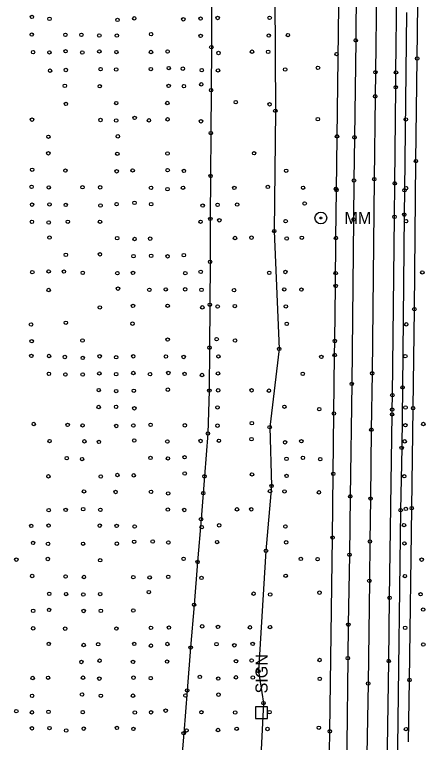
# Model space of a CAD drawing. Extents: x 20503438 to 20508873, y 7964251 to 7984667.
# Drawn here: x 20506372.5 to 20506616, y 7966287.3 to 7966710.9 of the extents above; entities that cross this region are included whole.
import ezdxf

# ---------------------------------------------------------------- set-up
doc = ezdxf.new("R2010")
doc.units = 0
for name, color, linetype in [('SurBreakLine', 7, 'Continuous'), ('SurDrainageArrowDown', 7, 'Continuous'), ('SurEdgeRoadPaved', 7, 'Continuous'), ('SurEdgeShoulderPaved', 7, 'Continuous'), ('SurGuardRailCable', 7, 'Continuous'), ('SurPointsNonDTM', 7, 'Continuous'), ('SurRoadPoints', 7, 'Continuous'), ('SurSurveyPoints', 7, 'Continuous')]:
    doc.layers.add(name, color=color, linetype=linetype)

msp = doc.modelspace()

# ---------------------------------------------------------------- linework, layer by layer
at = {"layer": 'SurBreakLine'}
msp.add_lwpolyline([(20506582.81, 7966724.92), (20506582.26, 7966677.31), (20506582.09, 7966663.27), (20506581.59, 7966615.11), (20506580.38, 7966502.13), (20506579.87, 7966469.3), (20506579.47, 7966429.21), (20506579.05, 7966404.24), (20506578.73, 7966381.34), (20506578.04, 7966321.61), (20506576.98, 7966259.67), (20506576.78, 7966244.96), (20506576.56, 7966215.41), (20506575.87, 7966179.43), (20506575.47, 7966138), (20506575.36, 7966120.77), (20506575.03, 7966091.32), (20506574.47, 7966046.48)], dxfattribs=at)
at = {"layer": 'SurDrainageArrowDown'}
for points in [[(20506523.75, 7966721.59), (20506524.08, 7966654.91), (20506523.46, 7966584.86), (20506526.32, 7966516.32), (20506520.79, 7966470.76), (20506521.88, 7966436.58), (20506518.64, 7966398.81), (20506514.26, 7966328.87), (20506517.2, 7966310.23), (20506515.68, 7966279.39), (20506513.5, 7966229.59), (20506515.33, 7966159.59), (20506514.55, 7966120.49), (20506514.84, 7966104.97), (20506511.67, 7966081.49), (20506510.59, 7966067.23)], [(20506487.04, 7966716.85), (20506486.89, 7966691.87), (20506486.74, 7966666.9), (20506486.58, 7966641.92), (20506486.43, 7966616.94), (20506486.28, 7966591.96), (20506486.13, 7966566.98), (20506485.98, 7966542.01), (20506485.83, 7966517.03), (20506485.68, 7966492.05), (20506484.9, 7966467.09), (20506482.89, 7966442.17), (20506480.87, 7966417.25), (20506478.86, 7966392.34), (20506476.85, 7966367.42), (20506474.83, 7966342.5), (20506472.82, 7966317.58), (20506470.8, 7966292.66), (20506468.79, 7966267.75)]]:
    msp.add_lwpolyline(points, dxfattribs=at)
at = {"layer": 'SurEdgeRoadPaved'}
for points in [[(20506571.13, 7966726.82), (20506570.83, 7966695.86), (20506570.09, 7966639.42), (20506569.8, 7966614.3), (20506569.59, 7966591.6), (20506568.51, 7966495.95), (20506567.62, 7966430.5), (20506567.22, 7966396.52), (20506566.49, 7966355.87), (20506566.21, 7966336.33), (20506565, 7966235.53), (20506564.23, 7966182.81), (20506563.62, 7966117.05), (20506563.45, 7966102.98), (20506562.98, 7966069.12), (20506561.69, 7965956.65)], [(20506586.39, 7966046.04), (20506586.58, 7966062.88), (20506587.24, 7966125.61), (20506587.67, 7966161.5), (20506587.93, 7966195.96), (20506590.01, 7966334.68), (20506590.5, 7966371.48), (20506591.96, 7966478.18), (20506591.99, 7966480.99), (20506592.1, 7966489.42), (20506593.34, 7966593.17), (20506593.52, 7966612.66), (20506594.1, 7966668.59), (20506594.21, 7966677.21), (20506594.79, 7966724.61)]]:
    msp.add_lwpolyline(points, dxfattribs=at)
at = {"layer": 'SurEdgeShoulderPaved'}
for points in [[(20506552.57, 7966028.45), (20506552.68, 7966057.72), (20506553.65, 7966115.57), (20506554.86, 7966229.07), (20506555.39, 7966269.1), (20506555.74, 7966293.81), (20506557.36, 7966406.54), (20506557.74, 7966443.63), (20506558.13, 7966478.73), (20506558.55, 7966512.75), (20506558.65, 7966520.93), (20506559.14, 7966552.93), (20506559.31, 7966580.85), (20506559.62, 7966608.8), (20506561.22, 7966731.44)], [(20506600.27, 7966712.13), (20506599.16, 7966608.62), (20506599.01, 7966594.45), (20506598.05, 7966493.9), (20506597.53, 7966458.7), (20506596.92, 7966422.46), (20506595.16, 7966284.71), (20506594.2, 7966234.33), (20506593.75, 7966203.67), (20506592.8, 7966094.73), (20506592.19, 7966059.31), (20506591.79, 7966030.9)]]:
    msp.add_lwpolyline(points, dxfattribs=at)
at = {"layer": 'SurGuardRailCable'}
msp.add_lwpolyline([(20506601.58, 7966287.7), (20506602.08, 7966323.65), (20506603.37, 7966423.64), (20506604.15, 7966481.82), (20506604.89, 7966539.46), (20506605.81, 7966625.62), (20506606.52, 7966685.31), (20506607.57, 7966764.47), (20506608.97, 7966864.46), (20506610.33, 7966964.45), (20506611.57, 7967064.43), (20506612.49, 7967145.99), (20506613.24, 7967217.79), (20506614.06, 7967289.17), (20506615.02, 7967359.71), (20506615.99, 7967430.36)], dxfattribs=at)
at = {"layer": 'SurPointsNonDTM'}
for centre in [(20506606.52, 7966685.31), (20506605.81, 7966625.62), (20506604.89, 7966539.46), (20506604.15, 7966481.82), (20506603.37, 7966423.64), (20506602.08, 7966323.65)]:
    msp.add_circle(centre, 1, dxfattribs=at)
at = {"layer": 'SurRoadPoints'}
msp.add_lwpolyline([(20506519.48, 7966304.63), (20506519.48, 7966304.63), (20506519.48, 7966308.06), (20506512.62, 7966308.06), (20506512.62, 7966301.2), (20506519.48, 7966301.2), (20506519.48, 7966304.63)], dxfattribs=at)
for radius in [3.43, 0.571]:
    msp.add_circle((20506550.55, 7966592.5), radius, dxfattribs=at)
at = {"layer": 'SurSurveyPoints'}
for centre in [(20506382.56, 7966709.49), (20506392.78, 7966708.38), (20506442.07, 7966708.66), (20506480.62, 7966708.52), (20506490.53, 7966708.88), (20506520.77, 7966708.94), (20506432.3, 7966707.76), (20506470.57, 7966708.12), (20506382.48, 7966699.22), (20506402.05, 7966699.05), (20506411.33, 7966699.09), (20506421.73, 7966698.69), (20506431.91, 7966698.64), (20506451.83, 7966699.44), (20506480.66, 7966698.44), (20506520.24, 7966698.63), (20506531.39, 7966698.92), (20506570.83, 7966695.86), (20506486.89, 7966691.87), (20506383.23, 7966688.99), (20506392.73, 7966688.86), (20506402.15, 7966689.51), (20506411.87, 7966688.78), (20506421.76, 7966689.43), (20506431.68, 7966689.04), (20506451.82, 7966689.06), (20506461.42, 7966689.35), (20506491.03, 7966688.52), (20506510.5, 7966689.26), (20506519.94, 7966689.16), (20506559.67, 7966687.88), (20506402.29, 7966678.63), (20506422.5, 7966679.08), (20506431.56, 7966678.92), (20506451.69, 7966679.13), (20506462.13, 7966679.73), (20506470.31, 7966679.37), (20506529.77, 7966678.9), (20506548.87, 7966679.86), (20506393.12, 7966678.21), (20506481.31, 7966678.54), (20506490.76, 7966678.38), (20506582.26, 7966677.31), (20506594.21, 7966677.21), (20506481.02, 7966670.25), (20506401.69, 7966669.42), (20506421.99, 7966669.14), (20506462.05, 7966669.34), (20506470.93, 7966669.18), (20506486.74, 7966666.9), (20506594.1, 7966668.59), (20506582.09, 7966663.27), (20506402.34, 7966658.87), (20506431.6, 7966659.37), (20506461.27, 7966659.38), (20506501.05, 7966659.92), (20506520.75, 7966658.66), (20506524.08, 7966654.91), (20506382.61, 7966649.72), (20506422.41, 7966649.52), (20506431.52, 7966649.25), (20506442.28, 7966650.73), (20506450.59, 7966649.31), (20506461.44, 7966649.88), (20506548.81, 7966649.99), (20506599.92, 7966649.86), (20506480.89, 7966648.77), (20506486.58, 7966641.92), (20506392.15, 7966639.77), (20506432.52, 7966639.99), (20506559.9, 7966640), (20506570.09, 7966639.42), (20506392.13, 7966630.14), (20506432.21, 7966629.89), (20506461.39, 7966630.01), (20506511.72, 7966630.18), (20506382.7, 7966620.55), (20506402.03, 7966620.1), (20506431.82, 7966619.67), (20506441.13, 7966620.17), (20506461.46, 7966620.31), (20506470.94, 7966619.9), (20506530.37, 7966619.97), (20506486.43, 7966616.94), (20506581.59, 7966615.11), (20506569.8, 7966614.3), (20506593.52, 7966612.66), (20506382.37, 7966610.63), (20506392.37, 7966610.27), (20506411.98, 7966610.37), (20506422.22, 7966610.35), (20506451.81, 7966610.07), (20506461.41, 7966609.27), (20506470.43, 7966610.1), (20506500.22, 7966610.01), (20506519.69, 7966610.58), (20506540.2, 7966610.11), (20506559.32, 7966609.51), (20506559.62, 7966608.8), (20506599.16, 7966608.62), (20506600.11, 7966609.85), (20506382.67, 7966600.27), (20506392.81, 7966600.38), (20506402.23, 7966600.1), (20506422.43, 7966599.78), (20506431.8, 7966600.54), (20506442.21, 7966601.33), (20506451.89, 7966600.54), (20506481.85, 7966599.71), (20506490.51, 7966600.15), (20506501.91, 7966600.3), (20506541.11, 7966600.94), (20506599.01, 7966594.45), (20506382.55, 7966590.28), (20506392.31, 7966589.85), (20506403.43, 7966590.32), (20506422.14, 7966590.29), (20506480.61, 7966590.29), (20506486.28, 7966591.96), (20506491.51, 7966591.14), (20506530.06, 7966590.65), (20506569.59, 7966591.6), (20506593.34, 7966593.17), (20506600.07, 7966590.64), (20506523.46, 7966584.86), (20506392.81, 7966581.1), (20506432.11, 7966580.76), (20506442.26, 7966580.27), (20506451.3, 7966580.48), (20506500.63, 7966580.84), (20506510.22, 7966581.06), (20506530.69, 7966580.56), (20506539.49, 7966581.01), (20506559.31, 7966580.85), (20506402.28, 7966571.08), (20506422.11, 7966571.35), (20506441.64, 7966570.28), (20506451.91, 7966570.49), (20506461.45, 7966570.2), (20506470.87, 7966570.87), (20506486.13, 7966566.98), (20506382.78, 7966560.98), (20506392.29, 7966561.42), (20506401.16, 7966561.3), (20506412.12, 7966560.61), (20506432.23, 7966560.38), (20506441.32, 7966560.52), (20506471.74, 7966560.38), (20506480.69, 7966561.14), (20506520.54, 7966560.57), (20506529.95, 7966561.09), (20506559.13, 7966560.42), (20506609.52, 7966560.84), (20506559.14, 7966552.93), (20506392.33, 7966550.57), (20506432.62, 7966551.39), (20506450.84, 7966550.68), (20506460.38, 7966550.94), (20506471.64, 7966551), (20506481.13, 7966550.69), (20506500.07, 7966550.52), (20506529.26, 7966550.94), (20506539.26, 7966550.84), (20506422.05, 7966540.44), (20506441.33, 7966541.34), (20506461.48, 7966541.44), (20506481.63, 7966540.49), (20506485.98, 7966542.01), (20506490.55, 7966541.01), (20506500.52, 7966541.22), (20506530.2, 7966541.05), (20506382.04, 7966530.53), (20506402.26, 7966531.52), (20506441.03, 7966530.98), (20506530.72, 7966530.9), (20506600.19, 7966530.59), (20506489.97, 7966521.97), (20506382.42, 7966520.78), (20506412, 7966521.23), (20506461.46, 7966521.73), (20506500.64, 7966521.18), (20506558.65, 7966520.93), (20506485.83, 7966517.03), (20506526.32, 7966516.32), (20506382.23, 7966512.25), (20506392.55, 7966512.18), (20506401.72, 7966511.61), (20506412.12, 7966511.06), (20506421.97, 7966512.01), (20506431.56, 7966511.47), (20506441.49, 7966512.01), (20506460.47, 7966511.92), (20506470.79, 7966511.62), (20506490.99, 7966511.95), (20506550.85, 7966511.65), (20506558.55, 7966512.75), (20506599.64, 7966512.11), (20506392.46, 7966501.79), (20506402.05, 7966501.42), (20506412.08, 7966501.41), (20506421.76, 7966502.07), (20506431.56, 7966501.62), (20506441.54, 7966502.27), (20506451.23, 7966501.64), (20506461.87, 7966502.3), (20506471.33, 7966501.77), (20506481.43, 7966501.12), (20506490.75, 7966502.04), (20506540.03, 7966501.79), (20506580.38, 7966502.13), (20506421.41, 7966492.35), (20506461.58, 7966492.59), (20506510.27, 7966492.21), (20506568.51, 7966495.95), (20506598.05, 7966493.9), (20506431.55, 7966491.78), (20506441.83, 7966491.96), (20506485.68, 7966492.05), (20506490.82, 7966492.18), (20506520.34, 7966492.01), (20506592.1, 7966489.42), (20506421.4, 7966482.49), (20506431.51, 7966482.59), (20506442.13, 7966481.76), (20506490.44, 7966482.28), (20506529.35, 7966482.64), (20506549.62, 7966481.23), (20506591.99, 7966480.99), (20506599.78, 7966482.23), (20506558.13, 7966478.73), (20506591.96, 7966478.18), (20506383.62, 7966472.59), (20506403.32, 7966472.09), (20506412.01, 7966471.78), (20506431.59, 7966471.46), (20506441.55, 7966471.77), (20506451.55, 7966472.13), (20506471.44, 7966471.85), (20506490.47, 7966471.62), (20506510.39, 7966473.11), (20506599.67, 7966471.88), (20506610.13, 7966472.59), (20506484.9, 7966467.09), (20506520.79, 7966470.76), (20506579.87, 7966469.3), (20506392.84, 7966462.66), (20506442.05, 7966463), (20506480.63, 7966462.75), (20506491.27, 7966462.87), (20506510.22, 7966463.81), (20506539.2, 7966462.58), (20506413.08, 7966462.51), (20506421.53, 7966462.21), (20506461.32, 7966462.45), (20506529.74, 7966461.98), (20506597.53, 7966458.7), (20506599.32, 7966462.51), (20506402.8, 7966452.73), (20506411.72, 7966452.19), (20506451.5, 7966452.88), (20506461.62, 7966452.59), (20506471.33, 7966453.27), (20506530.56, 7966452.34), (20506540.12, 7966452.91), (20506550.18, 7966452.18), (20506392.15, 7966442.14), (20506422.58, 7966442.05), (20506432.28, 7966442.92), (20506441.78, 7966442.72), (20506471.39, 7966443.81), (20506482.89, 7966442.17), (20506510.49, 7966443.29), (20506530.62, 7966442.42), (20506557.74, 7966443.63), (20506599.01, 7966442.23), (20506412.82, 7966433.37), (20506431.19, 7966433.05), (20506451.82, 7966433.15), (20506520.99, 7966433.59), (20506521.88, 7966436.58), (20506529.41, 7966433.38), (20506461.76, 7966432.23), (20506482.17, 7966432.35), (20506549.43, 7966432.84), (20506567.62, 7966430.5), (20506579.47, 7966429.21), (20506392.32, 7966422.49), (20506402.2, 7966422.64), (20506412.38, 7966423.05), (20506422.37, 7966422.68), (20506461.58, 7966422.81), (20506471.12, 7966422.59), (20506501.8, 7966422.96), (20506510.09, 7966422.97), (20506596.92, 7966422.46), (20506599.97, 7966423.21), (20506480.87, 7966417.25), (20506382.19, 7966413.31), (20506392.27, 7966413.52), (20506422.01, 7966413.46), (20506431.82, 7966413.3), (20506442.27, 7966412.99), (20506481.27, 7966412.61), (20506491.43, 7966413.67), (20506529.95, 7966413), (20506598.85, 7966413.78), (20506383.25, 7966403.43), (20506442, 7966404.11), (20506452.77, 7966404.27), (20506461.88, 7966403.64), (20506490.23, 7966403.92), (20506530.35, 7966403.78), (20506557.36, 7966406.54), (20506579.05, 7966404.24), (20506391.92, 7966402.87), (20506412.33, 7966402.92), (20506431.95, 7966402.98), (20506599.11, 7966403.11), (20506518.64, 7966398.81), (20506567.22, 7966396.52), (20506373.49, 7966393.68), (20506391.83, 7966394.08), (20506422.27, 7966393.34), (20506470.72, 7966394.16), (20506478.86, 7966392.34), (20506538.89, 7966394.13), (20506548.65, 7966393.98), (20506609.15, 7966393.7), (20506382.72, 7966384.14), (20506402.14, 7966383.86), (20506412.78, 7966383.57), (20506441.5, 7966383.5), (20506451.03, 7966383.33), (20506461.82, 7966383.7), (20506481.13, 7966383.06), (20506530.1, 7966384.3), (20506599.41, 7966384.13), (20506578.73, 7966381.34), (20506392.65, 7966373.8), (20506402.42, 7966373.64), (20506422.27, 7966373.65), (20506450.56, 7966374.8), (20506511.43, 7966373.88), (20506549.78, 7966374.48), (20506412.45, 7966373.39), (20506521.05, 7966373.41), (20506590.5, 7966371.48), (20506608.51, 7966373.54), (20506476.85, 7966367.42), (20506383.27, 7966363.91), (20506392.54, 7966364.43), (20506412.66, 7966363.83), (20506422.62, 7966363.88), (20506441.52, 7966364.07), (20506610.01, 7966364.61), (20506383.28, 7966353.7), (20506401.92, 7966353.54), (20506431.69, 7966353.56), (20506451.79, 7966354.02), (20506462.2, 7966354.15), (20506481.55, 7966354.86), (20506490.73, 7966354.55), (20506509.31, 7966354.28), (20506521, 7966354.44), (20506566.49, 7966355.87), (20506599.56, 7966354.03), (20506392.35, 7966344.66), (20506412.62, 7966344.01), (20506421.1, 7966344.44), (20506442.04, 7966344.64), (20506461.35, 7966344.59), (20506489.88, 7966344.5), (20506510.93, 7966344.66), (20506610.09, 7966344.29), (20506451.75, 7966343.63), (20506474.83, 7966342.5), (20506500.22, 7966343.83), (20506566.21, 7966336.33), (20506411.36, 7966334.14), (20506421.92, 7966334.9), (20506441.35, 7966334.19), (20506461.13, 7966334.36), (20506501.23, 7966334.57), (20506510.3, 7966335), (20506549.82, 7966335.29), (20506590.01, 7966334.68), (20506514.26, 7966328.87), (20506383.02, 7966324.8), (20506391.98, 7966324.97), (20506412.25, 7966325.01), (20506421.73, 7966324.43), (20506441.6, 7966325.04), (20506451.64, 7966324.73), (20506480.18, 7966325.45), (20506490.89, 7966324.47), (20506501.16, 7966325.19), (20506510.98, 7966325.11), (20506549.89, 7966324.33), (20506578.04, 7966321.61), (20506382.66, 7966314.42), (20506411.71, 7966315.19), (20506422.62, 7966314.5), (20506441.34, 7966314.53), (20506471.79, 7966314.66), (20506472.82, 7966317.58), (20506491.02, 7966315.13), (20506517.2, 7966310.23), (20506373.48, 7966305.54), (20506382.55, 7966304.82), (20506392.23, 7966305.12), (20506412.11, 7966304.93), (20506442.37, 7966304.76), (20506451.85, 7966304.86), (20506460.31, 7966305.82), (20506481.09, 7966304.87), (20506500.7, 7966304.72), (20506520.66, 7966304.93), (20506382.55, 7966295.53), (20506392.77, 7966295.68), (20506402.49, 7966294.29), (20506412.69, 7966295.34), (20506431.97, 7966295.77), (20506441.58, 7966295.19), (20506472.49, 7966294.3), (20506490.73, 7966294.54), (20506501.61, 7966295.27), (20506519.55, 7966295.12), (20506549.38, 7966295.88), (20506555.74, 7966293.81), (20506600.07, 7966295.08), (20506470.8, 7966292.66)]:
    msp.add_circle(centre, 1, dxfattribs=at)

# ---------------------------------------------------------------- texts
at = {"layer": 'SurRoadPoints'}
for s, rotation, p in [('MM', 360, (20506564.26, 7966589.01)), ('SIGN', 90, (20506519.55, 7966315.84))]:
    msp.add_text(s, height=6.995, rotation=rotation, dxfattribs=at).set_placement(p)

doc.saveas('drawing.dxf')
